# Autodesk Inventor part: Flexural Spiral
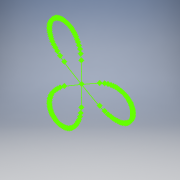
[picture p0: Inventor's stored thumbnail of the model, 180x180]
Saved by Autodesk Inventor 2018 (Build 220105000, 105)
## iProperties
Created: 2008-02
Part Number: Flexural Spiral
Document SubType Name: Modeling
Designer: Autodesk, Inc.
Density: 1 g/cm^3
Material: Generic
Appearance: Default
Author: Autodesk, Inc.
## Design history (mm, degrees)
sketch "Sketch1"
  geometry: 300 further points
  constraints: 300 other
